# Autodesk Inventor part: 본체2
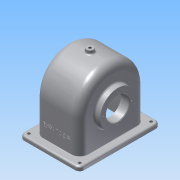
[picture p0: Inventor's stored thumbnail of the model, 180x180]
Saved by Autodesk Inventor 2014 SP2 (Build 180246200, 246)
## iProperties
Created: 2016-01
Part Number: 본체2
Material: 알루미늄 6061
Document SubType Name: Modeling
Designer: User
Mass: 842.835 g
Surface Area: 990.698 cm^2
Volume: 311.009 cm^3
Density: 2.71 g/cm^3
Appearance: 알루미늄 - 평지
Author: User
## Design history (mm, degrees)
sketch "스케치1"
  geometry: L1 (-57, 0)-(57, 0); L2 (57, 0)-(57, -64); L3 (57, -64)-(-57, -64); L4 (-57, -64)-(-57, 0); C1 r 57 at (0, 0); 2 further points
  constraints: 8 end point, 2 coincident, 2 parallel, 1 centre point, 1 horizontal, 1 midpoint, 1 perpendicular
  dimensions: "d0" = 114 diameter of C1; "d1" = 114 distance of L2.end L3.end; "d2" = 64 distance of L1.end L2.end
extrude "돌출1" new body sketch "스케치1" stored distance "d3" = 77; taper "d4" = 0 deg
feature "쉘1" dims "d7" = 6
sketch "스케치3"
  geometry: L1 (114, 0)-(114, -77) reference; L2 (0, 0)-(114, 0) reference; L3 (0, 0)-(0, -77) reference; L4 (114, -77)-(0, -77) reference; L5 (-13, 13.5)-(127, 13.5); L6 (127, 13.5)-(127, -90.5); L7 (127, -90.5)-(-13, -90.5); L8 (-13, -90.5)-(-13, 13.5); 3 further points
  constraints: 8 end point, 2 midpoint, 2 parallel, 1 horizontal, 1 horizontal alignment, 1 perpendicular, 1 vertical alignment
  dimensions: "d8" = 140 distance of L5.start L5.end; "d9" = 104 distance of L5.end L6.end
extrude "돌출2" join sketch "스케치3" distance "d10" = 7; taper "d11" = 0 deg
fillet "모깎기1" dims "d12" = 14
node "작업 평면1"
sketch "스케치6"
  geometry: C1 r 6 at (0, 0); 1 further point
  constraints: 1 centre point, 1 coincident
  dimensions: "d36" = 12 diameter of C1
extrude "돌출4" join sketch "스케치6" stored distance "d37" = 10; taper "d38" = 0 deg
hole "구멍2" diameter "d41" = 4.459; stored, may be unused: countersink angle "d45" = 90 deg, drill point angle "d47" = 118 deg; dims "d39" = 10, "d40" = 10, "d42" = 6, "d43" = 4, "d44" = 2, "d46" = 63
fillet "모깎기4" dims "d77" = 8
sketch "스케치9"
  geometry: A1 r 8 centre (119, 82.5) between (127, 82.5) and (119, 90.5) reference; A2 r 8 centre (-5, 82.5) between (-5, 90.5) and (-13, 82.5) reference; A3 r 8 centre (-5, -5.5) between (-13, -5.5) and (-5, -13.5) reference; A4 r 8 centre (119, -5.5) between (119, -13.5) and (127, -5.5) reference; 1 further point
hole "구멍5" sketch "스케치9" at (119, 82.5), (-5, 82.5), (119, -5.5), (-5, -5.5) diameter "d78" = 5; stored, may be unused: countersink angle "d82" = 90 deg, drill point angle "d84" = 118 deg; dims "d79" = 7, "d80" = 4, "d81" = 2, "d83" = 9
fillet "모깎기5" dims "d85" = 3
sketch "스케치10"
  geometry: L1 (49, 0)-(49, -57) reference; L2 (0, 0)-(49, 0) reference; L3 (0, -57)-(0, 0) reference; L4 (-1.387, -30.398)-(50.387, -30.398); L5 (50.387, -30.398)-(50.387, -37.602); L6 (50.387, -37.602)-(-1.387, -37.602); L7 (-1.387, -37.602)-(-1.387, -30.398); L8 (0, -34)-(49, -34); L9 (-19.5, -64)-(68.5, -64) reference; L10 (24.5, 0)-(24.5, -54); L11 (-14, 0)-(-14, -57) reference; L12 (68.5, -57)-(-19.5, -57) reference; 4 further points
  constraints: 4 end point, 4 midpoint, 2 point on line, 1 horizontal alignment, 1 perpendicular, 1 vertical alignment, 2 other
  dimensions: "d86" = 30 distance between parallel lines of L9 L8; "d87" = 38.5 distance between parallel lines of L11 L10
feature "엠보싱1" sketch "스케치10" dims "d8" = 140, "d9" = 104, "d88" = 0.5, "d89" = 0
sketch "스케치11"
  geometry: L1 (-51, -64)-(-51, 0) reference; L2 (51, -64)-(-51, -64) reference; L3 (51, 0)-(51, -64) reference; C1 r 20 at (0, -4) reference; A1 r 51 centre (0, 0) between (51, 0) and (-51, 0) reference
extrude "돌출5" cut sketch "스케치11" distance "d90" = 1; taper "d91" = 0 deg
sketch "스케치12"
  geometry: L1 (-51, -64)-(-51, 0) reference; L2 (51, -64)-(-51, -64) reference; L3 (51, 0)-(51, -64) reference; C1 r 38.908 at (0, -4) reference; A1 r 51 centre (0, 0) between (51, 0) and (-51, 0) reference
extrude "돌출6" cut sketch "스케치12" distance "d92" = 1; taper "d93" = 0 deg
sketch "스케치13"
  geometry: L1 (-4, 43.197)-(-4, -48.942); L2 (-64, -33.5)-(-64, 33.5) reference; L3 (16, 35.5)-(30.899, 35.5); L4 (24, 35.5)-(24, 19.5); L5 (24, 19.5)-(16, 19.5); L6 (16, 19.5)-(16, 35.5); L7 (0, 38.5)-(43, 38.5) reference; L8 (24, 19.5)-(39.943, 38.5); L9 (30.899, 35.5)-(33.416, 38.5); L10 (-4, 33.5)-(16, 33.5); L11 (-4, 38.5)-(33.416, 38.5); L12 (-4, 38.5)-(-4, 33.5); 1 further point
  constraints: 20 end point, 6 point on line, 3 parallel, 2 perpendicular, 1 collinear, 1 horizontal, 1 vertical
  dimensions: "d95" = 60 distance between parallel lines of L1 L2; "d96" = 20 distance between parallel lines of L1 L6; "d99" = 50 deg angle of L8 L5; "d100" = 5 distance between parallel lines of L8 L9; "d102" = 5 distance between parallel lines of L10 L11; "d103" = 56 diameter of L4 L1; "d104" = 19 distance between parallel lines of L11 L5; "d105" = 3 distance between parallel lines of L11 L3
revolve "회전3" stored, may be unused: angle "d106" = 90 deg
revolve "회전4" stored, may be unused: angle "d107" = 90 deg
sketch "스케치14"
  geometry: C1 r 20 at (0, -4) reference; C2 r 31 at (0, -4)
  constraints: 1 centre point, 1 coincident
  dimensions: "d108" = 62 diameter of C2
extrude "돌출7" join sketch "스케치14" distance "d109" = 10; taper "d110" = 0 deg
hole "구멍6" diameter "d113" = 40; stored, may be unused: countersink angle "d117" = 90 deg, drill point angle "d119" = 118 deg; dims "d111" = 10, "d112" = 10, "d114" = 6, "d115" = 4, "d116" = 2, "d118" = 8
chamfer "모따기3" distance "d120" = 1; stored, may be unused: second distance "d121" = 2, angle "d122" = 45 deg
fillet "모깎기6" dims "d123" = 3
sketch "스케치15"
  geometry: C1 r 31 at (0, 0) reference; 2 further points
  constraints: 1 vertical alignment
  dimensions: "d124" = 24 distance of C1.centre point (0, 24)
hole "구멍7" sketch "스케치15" at (0, 24) diameter "d125" = 2.459; stored, may be unused: countersink angle "d129" = 90 deg, drill point angle "d131" = 118 deg; dims "d126" = 6, "d127" = 4, "d128" = 2, "d130" = 8
sketch "스케치16"
  geometry: C1 r 21 at (0, 0) reference; 2 further points
  constraints: 1 vertical alignment
  dimensions: "d135" = 28 distance of C1.centre point (0, 28)
hole "구멍8" sketch "스케치16" at (0, 28) diameter "d136" = 2.459; stored, may be unused: countersink angle "d140" = 90 deg, drill point angle "d142" = 118 deg; dims "d137" = 7, "d138" = 4, "d139" = 2, "d141" = 9
fillet "모깎기7" dims "d146" = 9
fillet "모깎기8" dims "d147" = 3
fillet "모깎기9" dims "d148" = 1
node "솔리드1"
pattern_circular "원형 패턴3" dims angle "d133" = 360 deg
pattern_circular "원형 패턴4" dims angle "d144" = 360 deg
other parameters: "d35" = 63
